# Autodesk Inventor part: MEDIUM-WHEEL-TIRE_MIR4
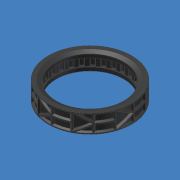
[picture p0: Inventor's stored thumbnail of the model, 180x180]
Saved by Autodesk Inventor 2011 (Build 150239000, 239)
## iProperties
Created: 2007-08
Part Number: MEDIUM-WHEEL-TIRE_MIR4
Material: Rubber
Document SubType Name: Modeling
Density: 0.93 g/cm^3
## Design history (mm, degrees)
derived "MEDIUM-WHEEL-TIRE.ipt"
body "Solid1"
tag "TaggingFeature2"
feature "DerivedBody::MEDIUM-WHEEL-TIRE.ipt" dims "d0" = 10
